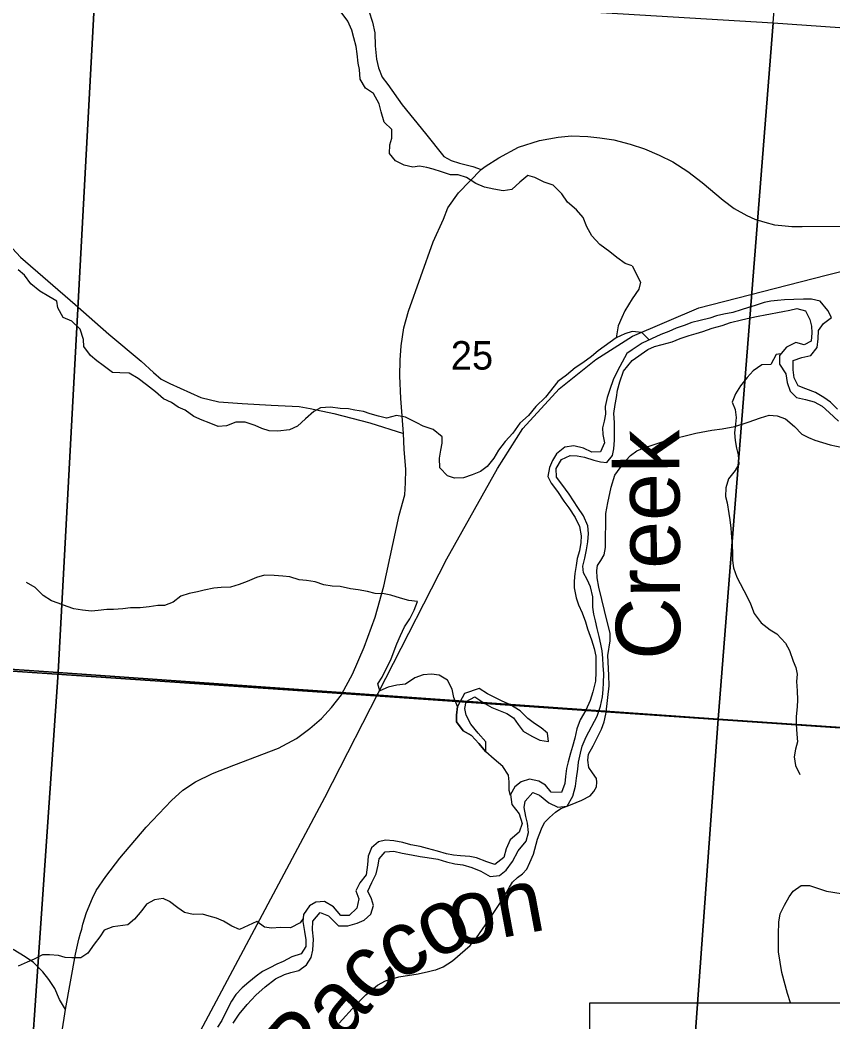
# Model space of a CAD drawing. Extents: x 0 to 34, y 0 to 22.
# Drawn here: x 6.354 to 7.55, y 18.398 to 19.87 of the extents above; entities that cross this region are included whole.
import ezdxf

# ---------------------------------------------------------------- set-up
doc = ezdxf.new("R2010")
doc.units = 0
for name, color, linetype in [('Default', 7, 'Continuous'), ('GM_X_County_Road', 7, 'Continuous'), ('GM_X_Major_River', 7, 'Continuous'), ('GM_X_Major_River_Text', 7, 'Continuous'), ('GM_X_Minor_Lake', 7, 'Continuous'), ('GM_X_Minor_River', 7, 'Continuous'), ('GM_X_Rail_Line', 7, 'Continuous'), ('GM_X_Section', 7, 'Continuous'), ('GM_X_Section_Text', 7, 'Continuous'), ('GM_X_State_Route', 7, 'Continuous'), ('GM_X_Township_Road', 7, 'Continuous'), ('SC_Scratch1', 7, 'Continuous'), ('SH_Text', 7, 'Continuous')]:
    doc.layers.add(name, color=color, linetype=linetype)

msp = doc.modelspace()

# ---------------------------------------------------------------- linework, layer by layer
at = {"layer": 'Default'}
msp.add_lwpolyline([(7.5178, 20.9), (6.5255, 20.9), (6.465, 19.9265), (7.462, 19.8663), (7.4997, 20.3683), (7.5295, 20.7659), (7.5396, 20.8985)], close=True, dxfattribs=at)
at = {"layer": 'GM_X_County_Road'}
msp.add_lwpolyline([(6.421, 18.416), (6.4124, 18.4307), (6.4054, 18.4472), (6.3968, 18.4604), (6.388, 18.4714), (6.3742, 18.4852), (6.362, 18.4937), (6.3442, 18.5044)], dxfattribs=at)
at = {"layer": 'GM_X_Major_River'}
for points in [[(7.5566, 19.2984), (7.546, 19.3086), (7.5361, 19.3155), (7.524, 19.3231), (7.51, 19.3284), (7.4986, 19.3326), (7.4929, 19.3447), (7.491, 19.3565), (7.491, 19.3702), (7.5039, 19.3743), (7.5172, 19.3774), (7.5263, 19.3891), (7.5278, 19.402), (7.5286, 19.4142), (7.5358, 19.4244), (7.5476, 19.4335), (7.5423, 19.4438), (7.5309, 19.4574), (7.5184, 19.4601), (7.5062, 19.4601), (7.4922, 19.4598), (7.4785, 19.459), (7.4683, 19.4583), (7.4584, 19.4571), (7.4486, 19.4552), (7.4353, 19.4511), (7.4254, 19.4481), (7.4148, 19.4446), (7.4023, 19.4405), (7.3894, 19.4382), (7.3787, 19.4356), (7.3685, 19.4325), (7.3544, 19.4291), (7.3423, 19.4261), (7.3309, 19.4216), (7.3191, 19.4174), (7.3085, 19.4129), (7.2968, 19.4083), (7.2827, 19.4019), (7.2691, 19.3954), (7.2547, 19.3859)], [(7.2547, 19.3701), (7.2774, 19.3863), (7.2873, 19.3905), (7.2986, 19.3935), (7.3131, 19.3973), (7.3252, 19.4022), (7.3385, 19.4068), (7.3484, 19.4098), (7.3586, 19.4128), (7.3719, 19.4174), (7.3867, 19.4215), (7.3992, 19.4257), (7.4151, 19.4298), (7.4281, 19.4329), (7.4398, 19.4351), (7.4501, 19.437), (7.4759, 19.4423), (7.4861, 19.4442), (7.4964, 19.4465), (7.5093, 19.443), (7.5157, 19.4301), (7.5183, 19.4203), (7.5187, 19.4108), (7.5176, 19.3986), (7.5073, 19.3933), (7.4952, 19.3967), (7.4815, 19.3895), (7.4713, 19.3774), (7.4713, 19.3645), (7.4804, 19.3504), (7.4826, 19.3379), (7.4868, 19.325), (7.4963, 19.3159), (7.5096, 19.3128), (7.5221, 19.3094), (7.5338, 19.3029), (7.5441, 19.2938), (7.5581, 19.2809)], [(7.2547, 19.3859), (7.2464, 19.3803), (7.2399, 19.3678), (7.2329, 19.355), (7.2264, 19.3417), (7.2214, 19.3273), (7.2175, 19.3156), (7.2148, 19.3024), (7.2154, 19.291), (7.2131, 19.2811), (7.2108, 19.2709), (7.2115, 19.2614), (7.214, 19.2493), (7.2079, 19.2357), (7.195, 19.2354), (7.1829, 19.2411), (7.1685, 19.2447), (7.1556, 19.2425), (7.143, 19.2331), (7.1372, 19.2233), (7.133, 19.2127), (7.1306, 19.1994), (7.1351, 19.1899), (7.1445, 19.1777), (7.1539, 19.1632), (7.1614, 19.1533), (7.1708, 19.1392), (7.1772, 19.1263), (7.1797, 19.1126), (7.1789, 19.1027), (7.1769, 19.0902), (7.1738, 19.0792), (7.1722, 19.0686), (7.1699, 19.0569), (7.1691, 19.0459), (7.1694, 19.036), (7.1719, 19.0212), (7.1757, 19.0109), (7.1809, 18.9991), (7.1857, 18.9858), (7.1887, 18.9756), (7.1947, 18.9596), (7.1987, 18.9467), (7.2009, 18.9353), (7.2012, 18.922), (7.2012, 18.9121), (7.2007, 18.8989), (7.1968, 18.8833), (7.1929, 18.8705), (7.1864, 18.8561), (7.1779, 18.8417), (7.1733, 18.8285), (7.1702, 18.8149), (7.1667, 18.8027), (7.164, 18.7929), (7.1601, 18.78), (7.1581, 18.7706), (7.1565, 18.7584), (7.1553, 18.7482), (7.1503, 18.735), (7.1355, 18.7358), (7.1272, 18.7457), (7.117, 18.7519), (7.1034, 18.7547), (7.0912, 18.7509), (7.0817, 18.7434), (7.0756, 18.7321), (7.0774, 18.7177), (7.0883, 18.7039), (7.0927, 18.6895), (7.0881, 18.6766), (7.0751, 18.6653), (7.069, 18.6521), (7.0659, 18.6396), (7.0525, 18.6291), (7.0408, 18.6333), (7.0253, 18.6391), (7.0158, 18.6411), (7.0018, 18.642), (6.9915, 18.6432), (6.9813, 18.6452), (6.9681, 18.6487), (6.9533, 18.6526), (6.9427, 18.6557), (6.929, 18.6584), (6.9173, 18.6616), (6.9041, 18.6643), (6.8915, 18.6652), (6.8813, 18.6626), (6.871, 18.6539), (6.8664, 18.6414), (6.8651, 18.6286), (6.8631, 18.6142), (6.854, 18.6025), (6.8482, 18.5907), (6.8527, 18.5786), (6.8495, 18.5653), (6.8385, 18.5544), (6.8259, 18.5545), (6.8154, 18.5671), (6.8022, 18.5751)], [(6.7956, 18.5589), (6.8077, 18.5539), (6.8228, 18.539), (6.8365, 18.5392), (6.8501, 18.5429), (6.8604, 18.5474), (6.87, 18.5561), (6.8742, 18.5689), (6.8709, 18.5788), (6.8656, 18.5899), (6.8714, 18.6027), (6.8779, 18.6156), (6.8807, 18.6281), (6.8826, 18.6375), (6.8914, 18.6481), (6.904, 18.6491), (6.9164, 18.646), (6.9301, 18.6433), (6.9426, 18.6409), (6.9528, 18.6397), (6.9687, 18.6369), (6.9812, 18.6334), (6.9937, 18.6303), (7.0055, 18.6287), (7.0187, 18.6251), (7.032, 18.6197), (7.0456, 18.6117), (7.0592, 18.6131), (7.0691, 18.621), (7.0783, 18.6338), (7.0868, 18.6493), (7.0986, 18.6636), (7.1021, 18.6765), (7.1003, 18.6898), (7.0981, 18.6997), (7.0955, 18.713), (7.0971, 18.7224), (7.1086, 18.7353), (7.1184, 18.731), (7.132, 18.7199), (7.1449, 18.7134), (7.1589, 18.7152), (7.1673, 18.7295), (7.1709, 18.7443), (7.1725, 18.756), (7.1744, 18.7693), (7.1756, 18.7799), (7.1784, 18.7928), (7.1811, 18.803), (7.1869, 18.817), (7.203, 18.8472), (7.2077, 18.862), (7.2108, 18.8756), (7.212, 18.8866), (7.2124, 18.8961), (7.2129, 18.9094), (7.2119, 18.9219), (7.2112, 18.9325), (7.2101, 18.9435), (7.2086, 18.953), (7.2061, 18.9644), (7.2031, 18.9762), (7.2005, 18.9876), (7.1983, 18.9971), (7.1965, 19.0074), (7.1966, 19.0225), (7.1933, 19.0374), (7.1884, 19.0484), (7.1828, 19.0579), (7.1821, 19.0678), (7.1848, 19.0795), (7.1872, 19.092), (7.1895, 19.1034), (7.1904, 19.1159), (7.1893, 19.1269), (7.183, 19.1418), (7.1747, 19.154), (7.1683, 19.1639), (7.1616, 19.1738), (7.151, 19.1883), (7.1431, 19.1986), (7.1428, 19.2111), (7.1505, 19.2247), (7.1635, 19.2303), (7.1737, 19.2298), (7.1843, 19.2282), (7.1979, 19.2236), (7.2078, 19.2209), (7.2172, 19.22), (7.2257, 19.2302), (7.2276, 19.2404), (7.2285, 19.2529), (7.2286, 19.267), (7.2283, 19.2791), (7.2276, 19.292), (7.2296, 19.3053), (7.2312, 19.3155), (7.2331, 19.3265), (7.2362, 19.3386), (7.2417, 19.3545), (7.2547, 19.3701)], [(6.8022, 18.5751), (6.7893, 18.5741), (6.7798, 18.5685), (6.771, 18.5556), (6.7701, 18.5454), (6.7727, 18.5306), (6.7745, 18.5188), (6.7744, 18.5086), (6.7679, 18.498), (6.7542, 18.4935), (6.7413, 18.4868), (6.7318, 18.4827), (6.7215, 18.4775), (6.7109, 18.4722), (6.7013, 18.4651), (6.6906, 18.4561), (6.6807, 18.4482), (6.6716, 18.4384), (6.665, 18.4286), (6.6581, 18.4142), (6.6512, 18.3998), (6.6447, 18.39)], [(6.6679, 18.3959), (6.6767, 18.4091), (6.6885, 18.4235), (6.7011, 18.437), (6.7149, 18.4495), (6.7301, 18.4611), (6.7431, 18.4675), (6.7526, 18.4704), (6.7643, 18.4737), (6.7754, 18.4816), (6.7823, 18.4926), (6.7846, 18.5036), (6.7859, 18.5195), (6.7845, 18.5332), (6.7849, 18.5461), (6.7956, 18.5589)]]:
    msp.add_lwpolyline(points, dxfattribs=at)
at = {"layer": 'GM_X_Minor_Lake'}
for points in [[(7.0395, 18.7948), (7.0391, 18.8096), (7.028, 18.8225), (7.0174, 18.8357), (7.0102, 18.849), (7.0082, 18.8585), (7.0101, 18.8691), (7.0233, 18.8759), (7.0378, 18.8661), (7.048, 18.8601), (7.0601, 18.8552), (7.07, 18.8514), (7.0798, 18.845), (7.0867, 18.8352), (7.0943, 18.8253), (7.1068, 18.8181), (7.1189, 18.8121), (7.1314, 18.8099), (7.1299, 18.8224), (7.1204, 18.8303), (7.1109, 18.8367), (7.101, 18.8439), (7.0896, 18.8553), (7.0745, 18.8643), (7.0631, 18.8692), (7.0536, 18.8745), (7.0419, 18.8802), (7.0294, 18.8881), (7.0081, 18.8807), (6.9976, 18.8615)], [(6.9976, 18.8615), (6.9962, 18.8486), (6.9962, 18.8391), (7.0057, 18.8259), (7.0182, 18.8187), (7.0292, 18.8073), (7.0395, 18.7948)]]:
    msp.add_lwpolyline(points, dxfattribs=at)
at = {"layer": 'GM_X_Minor_River'}
for points in [[(7.2545, 19.5092), (7.2443, 19.5126), (7.2317, 19.5217), (7.2215, 19.5296), (7.2071, 19.5406), (7.1953, 19.5534), (7.1877, 19.5667), (7.1823, 19.5803), (7.1728, 19.5917), (7.1595, 19.6026), (7.1512, 19.6151), (7.1383, 19.6276), (7.125, 19.6321), (7.1114, 19.6389), (7.1011, 19.6419), (7.0894, 19.6324), (7.0777, 19.6214), (7.0649, 19.6195), (7.0512, 19.6217), (7.0372, 19.6247), (7.0247, 19.63), (7.011, 19.639), (6.9985, 19.6428), (6.9872, 19.6431), (6.9743, 19.6473), (6.9618, 19.6514), (6.9523, 19.6537), (6.9417, 19.6555), (6.9319, 19.6544), (6.919, 19.6574), (6.9065, 19.6634), (6.8977, 19.6744), (6.8981, 19.6869), (6.9011, 19.6971), (6.901, 19.7097), (6.8897, 19.7202), (6.8851, 19.7354), (6.8824, 19.7475), (6.874, 19.7623), (6.8622, 19.7706), (6.8546, 19.7838), (6.8534, 19.7979), (6.8515, 19.8073), (6.85, 19.821), (6.8488, 19.8316), (6.8453, 19.8445), (6.8423, 19.8554), (6.8362, 19.8687), (6.8263, 19.8823)], [(7.2547, 19.4129), (7.2438, 19.4091), (7.231, 19.4034), (7.2045, 19.3844), (7.1947, 19.376), (7.1819, 19.3665), (7.1705, 19.3593), (7.1577, 19.3487), (7.1449, 19.3391), (7.1268, 19.3164), (7.1128, 19.3023), (7.1019, 19.2894), (7.0894, 19.278), (7.0789, 19.2635), (7.0676, 19.251), (7.0581, 19.2385), (7.051, 19.2267), (7.0412, 19.2142), (7.0314, 19.2069), (7.0193, 19.202), (7.0064, 19.1974), (6.9932, 19.197), (6.9829, 19.2004), (6.9715, 19.2121), (6.9711, 19.2265), (6.973, 19.2383), (6.9752, 19.2485), (6.9752, 19.258), (6.9619, 19.2686), (6.9471, 19.2735), (6.9376, 19.2784), (6.9213, 19.287), (6.9081, 19.2893), (6.8933, 19.2854), (6.8812, 19.2881), (6.8691, 19.2918), (6.8592, 19.2952), (6.8467, 19.2971), (6.8372, 19.299), (6.8248, 19.2997), (6.8107, 19.3015), (6.796, 19.3004), (6.7862, 19.295), (6.7741, 19.2844), (6.7624, 19.2734), (6.7507, 19.2684), (6.7336, 19.2661), (6.7204, 19.2668), (6.7098, 19.2702), (6.6999, 19.2747), (6.6851, 19.2796), (6.6715, 19.2796), (6.6579, 19.2739), (6.6454, 19.2731), (6.6325, 19.2787), (6.6223, 19.2825), (6.6098, 19.2878), (6.5969, 19.2969), (6.587, 19.3014), (6.5772, 19.3082), (6.5654, 19.3138), (6.5536, 19.324), (6.5404, 19.3342), (6.5278, 19.3437), (6.5149, 19.3516), (6.5009, 19.352), (6.4903, 19.3523), (6.4767, 19.3625), (6.4672, 19.3697), (6.4577, 19.3776), (6.4482, 19.3905), (6.4474, 19.4007), (6.4428, 19.4159), (6.4303, 19.428), (6.4178, 19.4333), (6.4098, 19.4476), (6.4082, 19.4575), (6.3965, 19.4639), (6.3832, 19.4722), (6.3703, 19.4828), (6.3608, 19.4953), (6.3513, 19.5032)], [(7.2545, 19.5092), (7.2669, 19.4851), (7.2643, 19.4748), (7.2546, 19.4606)], [(7.2546, 19.4606), (7.2435, 19.443), (7.2393, 19.4331), (7.234, 19.421), (7.231, 19.4034)], [(7.2794, 19.4003), (7.2685, 19.4111), (7.2547, 19.4129)], [(7.4733, 19.3798), (7.4664, 19.3791), (7.4586, 19.3642), (7.445, 19.3638), (7.4325, 19.3551), (7.4238, 19.3452), (7.414, 19.3327), (7.4064, 19.3209), (7.4015, 19.3088), (7.4057, 19.2982), (7.4076, 19.2864), (7.4065, 19.2766), (7.405, 19.264), (7.4057, 19.2527), (7.408, 19.2413), (7.4103, 19.2314), (7.4111, 19.2178), (7.4058, 19.2083), (7.3963, 19.1962), (7.3922, 19.1829), (7.3918, 19.1704), (7.3941, 19.1609), (7.3968, 19.1453), (7.3979, 19.1359), (7.3994, 19.1234), (7.4006, 19.1101), (7.4017, 19.0987), (7.4021, 19.0866), (7.4018, 19.0759), (7.4033, 19.0653), (7.4086, 19.0517), (7.4238, 19.0229), (7.4283, 19.0126), (7.434, 18.9982), (7.4443, 18.9846), (7.4575, 18.9743), (7.467, 18.9683), (7.4799, 18.9546), (7.4856, 18.9436), (7.4913, 18.9281), (7.4951, 18.9186), (7.497, 18.9091), (7.4963, 18.8981), (7.497, 18.8845), (7.4978, 18.8712), (7.4971, 18.8609), (7.4956, 18.8469), (7.4956, 18.8355), (7.4967, 18.8207), (7.4975, 18.8094), (7.4949, 18.7987), (7.4926, 18.7874), (7.4949, 18.7748), (7.501, 18.7616)], [(7.0757, 18.7307), (7.0734, 18.7381), (7.0737, 18.751), (7.0725, 18.7604), (7.0645, 18.7733), (7.0516, 18.7839), (7.0395, 18.7948), (7.0292, 18.8073), (7.0182, 18.8187), (7.0057, 18.8259), (6.9962, 18.8391), (6.9962, 18.8486), (6.9976, 18.8615), (6.9923, 18.8747), (6.9896, 18.8872), (6.9828, 18.9001), (6.9706, 18.9077), (6.9593, 18.9092), (6.9471, 18.908), (6.9347, 18.9038), (6.9211, 18.8943), (6.9082, 18.8927), (6.8957, 18.89), (6.8836, 18.8843), (6.8806, 18.8949), (6.887, 18.9044), (6.893, 18.9177), (6.8994, 18.9299), (6.9043, 18.9431), (6.9084, 18.9534), (6.914, 18.9659), (6.9197, 18.9784), (6.9276, 18.9906), (6.934, 19.0031), (6.9388, 19.016), (6.926, 19.0171), (6.9138, 19.0209), (6.8994, 19.0254), (6.8896, 19.0273), (6.8764, 19.0276), (6.865, 19.0306), (6.8517, 19.0329), (6.8404, 19.0344), (6.8248, 19.0381), (6.8131, 19.0385), (6.801, 19.0403), (6.7881, 19.0448), (6.7756, 19.0467), (6.7646, 19.0478), (6.751, 19.0523), (6.7408, 19.0531), (6.7279, 19.0542), (6.7139, 19.0545), (6.7021, 19.0511), (6.6882, 19.0453), (6.6764, 19.0408), (6.664, 19.037), (6.65, 19.0365), (6.6394, 19.0354), (6.625, 19.0323), (6.6152, 19.03), (6.603, 19.0277), (6.5909, 19.0235), (6.5796, 19.0148), (6.5668, 19.0098), (6.5569, 19.0101), (6.5441, 19.0078), (6.5308, 19.0067), (6.5168, 19.0063), (6.5055, 19.0051), (6.4918, 19.0039), (6.482, 19.0039), (6.4691, 19.0024), (6.4593, 19.0016), (6.446, 19.0031), (6.4332, 19.0049), (6.4237, 19.0083), (6.4104, 19.0132), (6.4006, 19.017), (6.3884, 19.0249), (6.3763, 19.0362), (6.3638, 19.0438)], [(6.7705, 18.5499), (6.7662, 18.5436), (6.7519, 18.5363), (6.7375, 18.5367), (6.7239, 18.5355), (6.714, 18.5374), (6.7023, 18.5457), (6.6898, 18.5396), (6.6769, 18.5339), (6.6659, 18.5388), (6.6534, 18.5459), (6.6432, 18.5505), (6.6322, 18.5531), (6.6224, 18.5561), (6.6091, 18.5557), (6.5959, 18.5587), (6.5864, 18.5655), (6.5742, 18.5749), (6.5648, 18.5791), (6.5519, 18.5772), (6.5402, 18.5711), (6.5334, 18.5616), (6.5224, 18.549), (6.5126, 18.5407), (6.4907, 18.5376), (6.4782, 18.5326), (6.4718, 18.5231), (6.4635, 18.5121), (6.4541, 18.4992), (6.4435, 18.4923), (6.4303, 18.4923), (6.4204, 18.4927), (6.4106, 18.4953), (6.3977, 18.4964), (6.3875, 18.4967), (6.375, 18.4903), (6.3648, 18.4857), (6.3516, 18.48)]]:
    msp.add_lwpolyline(points, dxfattribs=at)
at = {"layer": 'GM_X_Rail_Line'}
msp.add_lwpolyline([(6.5679, 18.2873), (6.8025, 18.728), (6.9819, 19.0787), (7.0563, 19.2113), (7.0938, 19.2701), (7.1472, 19.3284), (7.2009, 19.3716), (7.2548, 19.4059), (7.3524, 19.4473), (7.54, 19.4957), (7.6823, 19.531)], dxfattribs=at)
at = {"layer": 'GM_X_Section'}
for points in [[(6.465, 19.9265), (6.4104, 18.9115), (5.4174, 18.9797), (5.483, 19.983)], [(6.465, 19.9265), (7.462, 19.8663), (7.3808, 18.8429), (6.4104, 18.9115)], [(8.4423, 19.798), (8.3709, 18.7757), (7.3808, 18.8429), (7.462, 19.8663)], [(5.4174, 18.9797), (6.4104, 18.9115), (6.3391, 17.8836), (5.3412, 17.9492)], [(6.4104, 18.9115), (7.3808, 18.8429), (7.3065, 17.8168), (6.3391, 17.8836)], [(8.3709, 18.7757), (8.3007, 17.7677), (7.3065, 17.8168), (7.3808, 18.8429)]]:
    msp.add_lwpolyline(points, close=True, dxfattribs=at)
at = {"layer": 'GM_X_State_Route'}
for points in [[(6.918, 19.2627), (6.9141, 19.3144), (6.9128, 19.3474), (6.9135, 19.3707), (6.9147, 19.3918), (6.9187, 19.4181), (6.9254, 19.4425), (6.9618, 19.5444), (6.9768, 19.578), (6.9835, 19.5946), (6.9991, 19.6163), (7.0325, 19.6509), (7.0383, 19.655), (7.0585, 19.6679), (7.0875, 19.6836), (7.1184, 19.6934), (7.1456, 19.6983), (7.1652, 19.7001), (7.1894, 19.6995), (7.2068, 19.6973), (7.2276, 19.6943), (7.2517, 19.6882), (7.2726, 19.6811), (7.294, 19.6719), (7.3141, 19.6622), (7.3362, 19.6478), (7.3573, 19.6316), (7.3882, 19.6059), (7.4047, 19.5936), (7.4233, 19.5832), (7.435, 19.578), (7.4497, 19.5735), (7.464, 19.5695), (7.4747, 19.5683), (7.4894, 19.567), (7.5044, 19.567), (7.5653, 19.5673)], [(6.4067, 18.3245), (6.421, 18.416), (6.436, 18.4974), (6.4409, 18.5197), (6.4433, 18.5286), (6.4449, 18.5344), (6.4464, 18.5417), (6.4519, 18.5586), (6.4608, 18.5797), (6.4663, 18.591), (6.4803, 18.6118), (6.5008, 18.6387), (6.5395, 18.6843), (6.577, 18.7234), (6.5938, 18.7387), (6.6125, 18.7508), (6.6372, 18.7632), (6.6687, 18.7754), (6.7342, 18.8005), (6.7608, 18.8146), (6.7804, 18.8293), (6.7978, 18.8439), (6.8125, 18.8599), (6.8269, 18.8788), (6.8275, 18.8799), (6.8434, 18.9091), (6.8605, 18.9486), (6.8767, 18.9926), (6.8893, 19.0382), (6.9119, 19.1425), (6.9202, 19.1725), (6.9211, 19.1902), (6.9214, 19.2101), (6.9193, 19.2397), (6.918, 19.2627)]]:
    msp.add_lwpolyline(points, dxfattribs=at)
at = {"layer": 'GM_X_Township_Road'}
for points in [[(6.8673, 19.8842), (6.8728, 19.8674), (6.8761, 19.8515), (6.8767, 19.8325), (6.8783, 19.8129), (6.8816, 19.8001), (6.887, 19.7867), (6.895, 19.7756), (6.9162, 19.746), (6.9505, 19.7035), (6.9777, 19.6698), (6.9881, 19.664), (7.0003, 19.66), (7.0202, 19.6551), (7.0325, 19.6509)], [(6.3243, 19.5542), (6.3549, 19.5218), (6.4354, 19.4526), (6.4849, 19.4086), (6.5326, 19.3691), (6.5507, 19.3526), (6.5617, 19.3425), (6.5745, 19.3361), (6.6201, 19.3159), (6.6467, 19.3092), (6.681, 19.3067), (6.7235, 19.3046), (6.7648, 19.3025), (6.781, 19.2997), (6.8159, 19.2921), (6.8685, 19.2783), (6.918, 19.2627)], [(6.9629, 18.4739), (6.9655, 18.4745), (6.9766, 18.479), (6.9901, 18.4875), (7.0091, 18.5037), (7.0161, 18.5101), (7.0254, 18.5213), (7.0431, 18.5472), (7.0626, 18.5762), (7.0742, 18.596), (7.0786, 18.6035), (7.0856, 18.6104), (7.0932, 18.6155), (7.0996, 18.6224), (7.104, 18.6323), (7.1096, 18.6445), (7.1154, 18.6664), (7.1209, 18.6816), (7.1257, 18.6911), (7.1329, 18.6985), (7.1417, 18.7062), (7.1496, 18.7114), (7.1638, 18.7169), (7.1802, 18.7236), (7.1925, 18.7304), (7.1982, 18.7367), (7.202, 18.7433), (7.2024, 18.7503), (7.2018, 18.7555), (7.1959, 18.7642), (7.1908, 18.772), (7.1891, 18.7828), (7.1904, 18.7914), (7.1971, 18.8035), (7.2094, 18.8284), (7.2134, 18.8392), (7.2157, 18.8504), (7.2161, 18.8534), (7.2208, 18.892), (7.22, 18.9076), (7.2186, 18.9366), (7.2221, 18.9581), (7.2219, 18.9691), (7.2183, 18.9847), (7.2054, 19.0369), (7.203, 19.0505), (7.2026, 19.0614), (7.2034, 19.069), (7.2085, 19.0762), (7.2132, 19.0844), (7.2153, 19.0954), (7.2158, 19.1453), (7.2185, 19.1607), (7.2235, 19.1839), (7.2288, 19.2016), (7.2366, 19.2122), (7.2451, 19.2232), (7.2521, 19.2304), (7.2611, 19.2371), (7.2723, 19.2419), (7.3047, 19.2526), (7.3482, 19.2633), (7.3716, 19.2678), (7.3868, 19.2695), (7.4056, 19.273), (7.4249, 19.2792), (7.4434, 19.2859), (7.4558, 19.2895), (7.4679, 19.2889), (7.48, 19.2842), (7.4931, 19.2732), (7.5039, 19.2619), (7.514, 19.257), (7.5231, 19.2532), (7.5457, 19.2462), (7.5738, 19.2403)], [(7.4874, 18.426), (7.4828, 18.4397), (7.4746, 18.4704), (7.4697, 18.5011), (7.4696, 18.527), (7.4701, 18.5445), (7.4723, 18.5566), (7.4783, 18.5696), (7.4855, 18.5817), (7.4914, 18.5901), (7.5028, 18.5982), (7.5153, 18.5982), (7.5402, 18.5902), (7.5618, 18.5867)], [(6.8235, 18.396), (6.8474, 18.4224), (6.8628, 18.4378), (6.8799, 18.452), (6.8919, 18.4582), (6.9113, 18.4644), (6.9399, 18.4687), (6.9549, 18.4721), (6.9629, 18.4739)]]:
    msp.add_lwpolyline(points, dxfattribs=at)
at = {"layer": 'SC_Scratch1'}
for points in [[(8.9, 18.7389), (8.9, 20.9), (5.53, 20.9), (5.4955, 20.3864), (5.4469, 19.6641), (5.4089, 19.0989), (5.4007, 18.9779), (5.4885, 18.9719), (5.9889, 18.9377), (6.8273, 18.8804), (7.2159, 18.8539), (8.2061, 18.7863)], [(5.0535, 14.1), (8.9, 14.1), (8.9, 18.7389), (8.2061, 18.7863), (7.2159, 18.8539), (6.8273, 18.8804), (5.9889, 18.9377), (5.4885, 18.9719), (5.4007, 18.9779), (5.3662, 18.4999), (5.3506, 18.2846), (5.2869, 17.4026), (5.2761, 17.2534), (5.1794, 15.9156), (5.1049, 14.8414), (5.0814, 14.5016)]]:
    msp.add_lwpolyline(points, close=True, dxfattribs=at)
at = {"layer": 'SH_Text'}
msp.add_lwpolyline([(8.5782, 18.186), (7.1921, 18.186), (7.1921, 18.426), (8.5782, 18.426)], close=True, dxfattribs=at)

# ---------------------------------------------------------------- texts
at = {"layer": 'GM_X_Major_River_Text'}
for s, height, rotation, p in [('Creek', 0.09469, 90.2869, (7.3254, 18.9304)), ('on', 0.09469, 10.5706, (6.9915, 18.508)), ('co', 0.0947, 28.5715, (6.9079, 18.4565)), ('Rac', 0.0947, 48.5724, (6.7677, 18.2996))]:
    msp.add_text(s, height=height, rotation=rotation, dxfattribs=at).set_placement(p)
at = {"layer": 'GM_X_Section_Text'}
msp.add_text('25', height=0.04186, rotation=0, dxfattribs=at).set_placement((6.9877, 19.3567))

doc.saveas('drawing.dxf')
